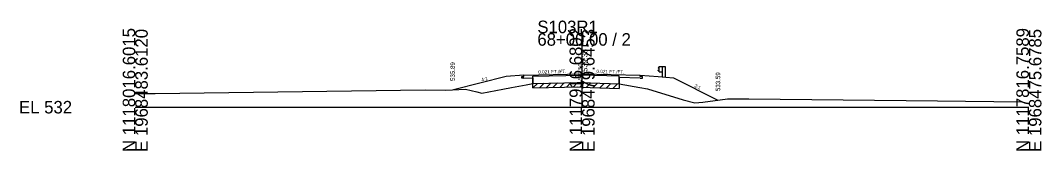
# Model space of a CAD drawing. Extents: x -26 to 203, y -10 to 12018.
# Drawn here: x -25.7 to 202.8, y 7990.3 to 8019.4 of the extents above; entities that cross this region are included whole.
import ezdxf

# ---------------------------------------------------------------- set-up
doc = ezdxf.new("R2010")
doc.units = 0
for name, color, linetype in [('Level 10', 7, 'Continuous'), ('Level 11', 7, 'Continuous'), ('Level 12', 7, 'Continuous'), ('Level 24', 7, 'Continuous'), ('Level 32', 7, 'Continuous'), ('Level 33', 7, 'Continuous'), ('Level 53', 7, 'Continuous'), ('Level 59', 7, 'Continuous'), ('Level 6', 7, 'Continuous'), ('Level 60', 7, 'Continuous'), ('Level 61', 7, 'Continuous'), ('Level 63', 7, 'Continuous'), ('Level 7', 7, 'Continuous')]:
    doc.layers.add(name, color=color, linetype=linetype)

msp = doc.modelspace()

# ---------------------------------------------------------------- linework, layer by layer
at = {"layer": 'Level 11'}
for p, q in [((86.5, 8006.85), (87, 8006.86)), ((86.5, 8006.49), (86.5, 8006.85)), ((87, 8006.5), (86.5, 8006.49)), ((87, 8006.86), (87, 8007.18)), ((113, 8006.86), (113, 8007.18)), ((113.5, 8006.85), (113, 8006.86)), ((113, 8006.5), (113.5, 8006.49)), ((113.5, 8006.49), (113.5, 8006.85))]:
    msp.add_line(p, q, dxfattribs=at)
at = {"layer": 'Level 12'}
for p, q in [((87, 8006.5), (88.99, 8006.54)), ((88.99, 8006.54), (88.99, 8005.29)), ((108.3, 8006.6), (108.3, 8005.2)), ((113, 8006.5), (108.3, 8006.6))]:
    msp.add_line(p, q, dxfattribs=at)
at = {"layer": 'Level 24'}
for p, q in [((117.27, 8009.02), (117, 8008.82)), ((117, 8008.82), (117, 8008.77)), ((117, 8008.77), (117.27, 8008.57)), ((117, 8008.25), (117.27, 8008.45)), ((117, 8008.2), (117, 8008.25)), ((117.27, 8008), (117, 8008.2)), ((117.27, 8007.93), (117.27, 8009.09)), ((117.27, 8009.09), (117.94, 8009.09)), ((117.27, 8007.93), (117.94, 8007.93)), ((117.94, 8009.09), (117.94, 8006.76)), ((117.94, 8009.09), (118.6, 8009.09)), ((118.6, 8009.09), (118.6, 8006.71))]:
    msp.add_line(p, q, dxfattribs=at)
at = {"layer": 'Level 53'}
for p, q in [((88.99, 8006.9), (100, 8007.13)), ((88.99, 8005.29), (88.99, 8006.9)), ((108.3, 8006.96), (100, 8007.13)), ((108.3, 8005.2), (108.3, 8006.96))]:
    msp.add_line(p, q, dxfattribs=at)
at = {"layer": 'Level 59'}
for p, q in [((87, 8007.18), (100, 8007.45)), ((100, 8007.45), (113, 8007.18))]:
    msp.add_line(p, q, dxfattribs=at)
at = {"layer": 'Level 6'}
for p, q in [((87, 8007.18), (83, 8006.84)), ((113, 8007.18), (117, 8006.84)), ((117, 8006.84), (120.5, 8006.55))]:
    msp.add_line(p, q, dxfattribs=at)
at = {"layer": 'Level 60'}
for p, q in [((96.08, 8005.45), (98.94, 8005.51)), ((98.94, 8005.51), (100, 8005.48)), ((4.43, 8003.07), (64.87, 8003.84)), ((64.87, 8003.84), (69.53, 8003.83)), ((69.53, 8003.83), (73.88, 8003.99)), ((73.88, 8003.99), (76.48, 8003.42)), ((76.48, 8003.42), (77.59, 8003.13)), ((77.59, 8003.13), (82.3, 8004.03)), ((82.3, 8004.03), (84.18, 8004.41)), ((84.18, 8004.41), (87.47, 8005.03)), ((87.47, 8005.03), (88.99, 8005.29)), ((88.99, 8005.29), (96.08, 8005.45)), ((100, 8005.48), (101.79, 8005.42)), ((101.79, 8005.42), (108.3, 8005.2)), ((108.3, 8005.2), (112.96, 8004.38)), ((112.96, 8004.38), (114.63, 8004.09)), ((114.63, 8004.09), (122.66, 8001.66)), ((0, 8003.04), (4.43, 8003.07)), ((122.66, 8001.66), (125.25, 8000.96)), ((125.25, 8000.96), (127.06, 8001.11)), ((127.06, 8001.11), (132.53, 8001.9)), ((132.53, 8001.9), (137.34, 8001.89)), ((137.34, 8001.89), (179.52, 8001.41)), ((179.52, 8001.41), (198.45, 8001.22))]:
    msp.add_line(p, q, dxfattribs=at)
at = {"layer": 'Level 61'}
for p, q in [((97.99, 8004.49), (99.01, 8005.51)), ((88.99, 8004.29), (90.02, 8005.31)), ((88.99, 8004.29), (88.99, 8005.29)), ((88.99, 8004.29), (96.08, 8004.45)), ((90.49, 8004.32), (91.52, 8005.35)), ((91.99, 8004.36), (93.02, 8005.38)), ((93.49, 8004.39), (94.52, 8005.42)), ((94.99, 8004.43), (96.02, 8005.45)), ((96.08, 8004.45), (98.94, 8004.51)), ((96.49, 8004.46), (97.51, 8005.48)), ((98.94, 8004.51), (100, 8004.48)), ((99.49, 8004.5), (100.46, 8005.46)), ((100, 8004.48), (101.79, 8004.42)), ((100.99, 8004.45), (101.96, 8005.41)), ((101.79, 8004.42), (108.3, 8004.2)), ((102.49, 8004.4), (103.46, 8005.36)), ((103.99, 8004.35), (104.96, 8005.31)), ((105.49, 8004.3), (106.46, 8005.26)), ((106.99, 8004.25), (107.96, 8005.22)), ((108.3, 8005.2), (108.3, 8004.2))]:
    msp.add_line(p, q, dxfattribs=at)
at = {"layer": 'Level 63'}
for p, q in [((100, 8000), (100, 8016.54)), ((0, 8000), (100, 8000)), ((100, 8000), (200, 8000))]:
    msp.add_line(p, q, dxfattribs=at)
at = {"layer": 'Level 7'}
for p, q in [((83, 8006.84), (71.2, 8003.89)), ((120.5, 8006.55), (130.42, 8001.59))]:
    msp.add_line(p, q, dxfattribs=at)

# ---------------------------------------------------------------- texts
at = {"layer": 'Level 10'}
msp.add_text(' 537.50', height=0.9, rotation=90, dxfattribs=at).set_placement((100, 8005.62))
at = {"layer": 'Level 32'}
for s, rotation, p in [('0.021 FT./FT.', 1.1916, (90.21, 8007.49)), ('0.021 FT./FT.', 358.8084, (103.22, 8007.63)), ('4:1', 14.0362, (77.57, 8005.73)), ('2:1', 333.4349, (125.07, 8004.55))]:
    msp.add_text(s, height=0.75, rotation=rotation, dxfattribs=at).set_placement(p)
at = {"layer": 'Level 33'}
for s, p in [('535.89', (71.53, 8005.84)), ('533.59', (130.92, 8003.59))]:
    msp.add_text(s, height=1, rotation=90, dxfattribs=at).set_placement(p)
at = {"layer": 'Level 59'}
msp.add_text(' 539.38', height=1.2, rotation=90, dxfattribs=at).set_placement((101.2, 8007.45))
at = {"layer": 'Level 63'}
for s, p in [('S103R1', (90, 8016.54)), ('68+00.00 / 2', (90, 8013.74)), ('EL 532', (-26, 7998.6))]:
    msp.add_text(s, height=2.8, dxfattribs=at).set_placement(p)
for s, p in [('N 1118016.6015', (0, 7990)), ('E 1968483.6120', (2.8, 7990)), ('N 1117916.6802', (100, 7990)), ('E 1968479.6453', (102.8, 7990)), ('N 1117816.7589', (200, 7990)), ('E 1968475.6785', (202.8, 7990))]:
    msp.add_text(s, height=2.8, rotation=90, dxfattribs=at).set_placement(p)

doc.saveas('drawing.dxf')
